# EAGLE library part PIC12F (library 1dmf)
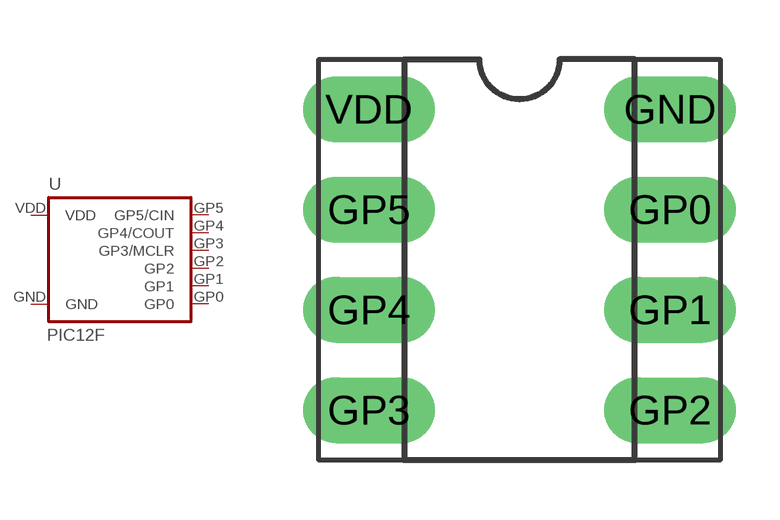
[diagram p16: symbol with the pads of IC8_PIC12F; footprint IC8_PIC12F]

Designator prefix -

## PIC12F  [IC8_PIC12F]
GND  GND  pwr
GP0  GP0
GP1  GP1
GP2  GP2
GP3  GP3/MCLR  in
GP4  GP4/COUT
GP5  GP5/CIN
VDD  VDD  pwr

## Footprint IC8_PIC12F (pad centres in mm)
drill 0.813 pad 1.676 long: GND 3.81,3.81; GP0 3.81,1.27; GP1 3.81,-1.27; GP2 3.81,-3.81; GP3 -3.81,-3.81; GP4 -3.81,-1.27; GP5 -3.81,1.27; VDD -3.81,3.81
